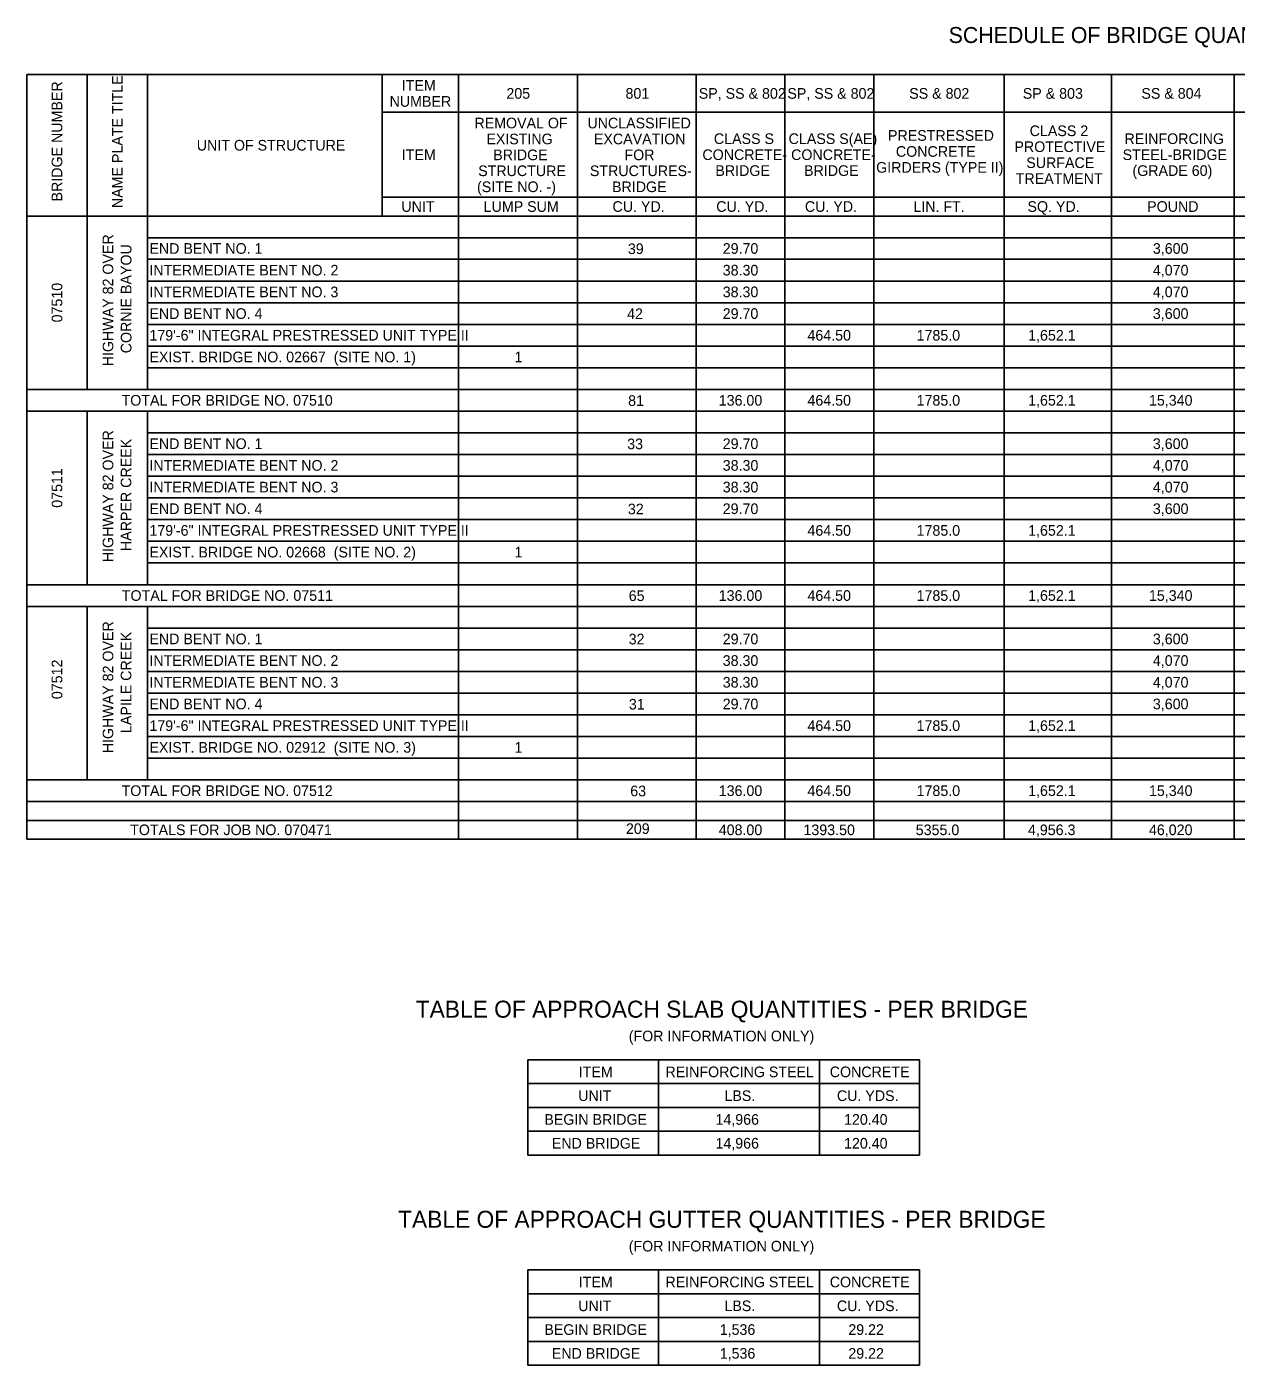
# Model space of a CAD drawing. Extents: x 978208 to 1610025, y 186514 to 1526540.
# Drawn here: x 978207.71 to 978221.92, y 1526243.05 to 1526258.78 of the extents above; entities that cross this region are included whole.
import ezdxf

# ---------------------------------------------------------------- set-up
doc = ezdxf.new("R2010")
doc.units = 0
for name, color, linetype in [('B_Dimensions', 7, 'Continuous'), ('B_Text', 7, 'Continuous'), ('B_Title Text', 7, 'Continuous')]:
    doc.layers.add(name, color=color, linetype=linetype)

msp = doc.modelspace()

# ---------------------------------------------------------------- linework, layer by layer
at = {"layer": 'B_Dimensions'}
msp.add_line((978207.713, 1526258.214), (978207.713, 1526258.214), dxfattribs=at)
at = {"layer": 'B_Text'}
for p, q in [((978207.713, 1526249.229), (978207.713, 1526258.214)), ((978207.713, 1526258.214), (978234.856, 1526258.214)), ((978208.422, 1526254.514), (978208.422, 1526258.214)), ((978209.131, 1526254.514), (978209.131, 1526258.214)), ((978211.886, 1526256.552), (978211.886, 1526258.214)), ((978212.784, 1526249.229), (978212.784, 1526258.214)), ((978214.18, 1526249.229), (978214.18, 1526258.214)), ((978215.576, 1526249.229), (978215.576, 1526258.214)), ((978216.618, 1526249.229), (978216.618, 1526258.214)), ((978217.66, 1526249.229), (978217.66, 1526258.214)), ((978219.191, 1526249.229), (978219.191, 1526258.214)), ((978220.452, 1526249.229), (978220.452, 1526258.214)), ((978221.892, 1526249.229), (978221.892, 1526258.214)), ((978211.886, 1526257.771), (978234.856, 1526257.771)), ((978211.886, 1526256.774), (978234.856, 1526256.774)), ((978207.713, 1526256.552), (978234.856, 1526256.552)), ((978209.131, 1526256.297), (978234.856, 1526256.297)), ((978209.131, 1526256.043), (978234.856, 1526256.043)), ((978209.131, 1526255.788), (978234.856, 1526255.788)), ((978209.131, 1526255.533), (978234.856, 1526255.533)), ((978209.131, 1526255.278), (978234.856, 1526255.278)), ((978209.131, 1526255.023), (978234.856, 1526255.023)), ((978209.131, 1526254.768), (978234.856, 1526254.768)), ((978207.713, 1526254.514), (978234.856, 1526254.514)), ((978207.713, 1526254.259), (978234.856, 1526254.259)), ((978208.422, 1526254.259), (978208.422, 1526252.22)), ((978209.131, 1526254.259), (978209.131, 1526252.22)), ((978209.131, 1526254.004), (978234.856, 1526254.004)), ((978209.131, 1526253.749), (978234.856, 1526253.749)), ((978209.131, 1526253.494), (978234.856, 1526253.494)), ((978209.131, 1526253.239), (978234.856, 1526253.239)), ((978209.131, 1526252.985), (978234.856, 1526252.985)), ((978209.131, 1526252.73), (978234.856, 1526252.73)), ((978209.131, 1526252.475), (978234.856, 1526252.475)), ((978207.713, 1526252.22), (978234.856, 1526252.22)), ((978207.713, 1526251.965), (978234.856, 1526251.965)), ((978208.422, 1526251.965), (978208.422, 1526249.927)), ((978209.131, 1526251.965), (978209.131, 1526249.927)), ((978209.131, 1526251.71), (978234.856, 1526251.71)), ((978209.131, 1526251.456), (978234.856, 1526251.456)), ((978209.131, 1526251.201), (978234.856, 1526251.201)), ((978209.131, 1526250.946), (978234.856, 1526250.946)), ((978209.131, 1526250.691), (978234.856, 1526250.691)), ((978209.131, 1526250.436), (978234.856, 1526250.436)), ((978209.131, 1526250.181), (978234.856, 1526250.181)), ((978207.713, 1526249.927), (978234.856, 1526249.927)), ((978207.713, 1526249.672), (978234.856, 1526249.672)), ((978207.713, 1526249.45), (978234.856, 1526249.45)), ((978207.713, 1526249.229), (978234.856, 1526249.229)), ((978213.598, 1526245.517), (978213.598, 1526246.637)), ((978213.598, 1526246.637), (978218.197, 1526246.637)), ((978215.131, 1526245.517), (978215.131, 1526246.637)), ((978217.024, 1526245.517), (978217.024, 1526246.637)), ((978218.197, 1526245.517), (978218.197, 1526246.637)), ((978213.598, 1526246.357), (978218.197, 1526246.357)), ((978213.598, 1526246.077), (978218.197, 1526246.077)), ((978213.598, 1526245.797), (978218.197, 1526245.797)), ((978213.598, 1526245.517), (978218.197, 1526245.517)), ((978213.598, 1526243.048), (978213.598, 1526244.168)), ((978213.598, 1526244.168), (978218.197, 1526244.168)), ((978215.131, 1526243.048), (978215.131, 1526244.168)), ((978217.024, 1526243.048), (978217.024, 1526244.168)), ((978218.197, 1526243.048), (978218.197, 1526244.168)), ((978213.598, 1526243.888), (978218.197, 1526243.888)), ((978213.598, 1526243.608), (978218.197, 1526243.608)), ((978213.598, 1526243.328), (978218.197, 1526243.328)), ((978213.598, 1526243.048), (978218.197, 1526243.048))]:
    msp.add_line(p, q, dxfattribs=at)

# ---------------------------------------------------------------- texts
for s, height, p in [('SCHEDULE OF BRIDGE QUANTITIES', 0.1875, (978218.54, 1526258.585)), ('ITEM', 0.125, (978212.118, 1526258.024)), ('NUMBER', 0.125, (978211.974, 1526257.836)), ('205', 0.125, (978213.346, 1526257.93)), ('801', 0.125, (978214.745, 1526257.93)), ('SP, SS & 802', 0.125, (978215.605, 1526257.93)), ('SP, SS & 802', 0.125, (978216.646, 1526257.93)), ('SS & 802', 0.125, (978218.077, 1526257.93)), ('SP & 803', 0.125, (978219.411, 1526257.93)), ('SS & 804', 0.125, (978220.804, 1526257.93)), ('REMOVAL OF', 0.1248, (978212.971, 1526257.582)), ('UNCLASSIFIED', 0.1248, (978214.298, 1526257.582)), ('EXISTING', 0.1248, (978213.111, 1526257.395)), ('EXCAVATION', 0.1248, (978214.374, 1526257.395)), ('CLASS S', 0.125, (978215.783, 1526257.398)), ('CLASS S(AE)', 0.125, (978216.661, 1526257.398)), ('    PRESTRESSED ', 0.125, (978217.642, 1526257.436)), ('CLASS 2', 0.125, (978219.492, 1526257.491)), ('REINFORCING', 0.125, (978220.605, 1526257.398)), ('UNIT OF STRUCTURE', 0.125, (978209.709, 1526257.321)), ('ITEM', 0.125, (978212.118, 1526257.21)), ('BRIDGE', 0.1248, (978213.191, 1526257.208)), ('FOR', 0.1248, (978214.733, 1526257.208)), ('CONCRETE-', 0.125, (978215.648, 1526257.21)), ('CONCRETE-', 0.125, (978216.69, 1526257.21)), ('      CONCRETE ', 0.125, (978217.642, 1526257.248)), ('PROTECTIVE', 0.125, (978219.313, 1526257.304)), ('STEEL-BRIDGE', 0.125, (978220.584, 1526257.21)), ('BRIDGE', 0.125, (978215.8, 1526257.023)), ('BRIDGE', 0.125, (978216.842, 1526257.023)), (' GIRDERS (TYPE II)', 0.125, (978217.642, 1526257.061)), ('SURFACE', 0.125, (978219.452, 1526257.116)), ('(GRADE 60)', 0.125, (978220.699, 1526257.023)), ('STRUCTURE', 0.1248, (978213.015, 1526257.021)), ('STRUCTURES-', 0.1248, (978214.327, 1526257.021)), ('TREATMENT', 0.125, (978219.328, 1526256.929)), ('(SITE NO. -)', 0.1248, (978213.001, 1526256.833)), ('BRIDGE', 0.1248, (978214.587, 1526256.833)), ('UNIT', 0.125, (978212.112, 1526256.601)), ('LUMP SUM', 0.125, (978213.079, 1526256.601)), ('CU. YD.', 0.125, (978214.592, 1526256.601)), ('CU. YD.', 0.125, (978215.811, 1526256.601)), ('CU. YD.', 0.125, (978216.852, 1526256.601)), ('LIN. FT.', 0.125, (978218.126, 1526256.601)), ('SQ. YD.', 0.125, (978219.466, 1526256.601)), ('POUND', 0.125, (978220.872, 1526256.601)), ('END BENT NO. 1', 0.125, (978209.153, 1526256.108)), ('39', 0.1248, (978214.773, 1526256.105)), ('29.70', 0.125, (978215.887, 1526256.108)), ('3,600', 0.125, (978220.939, 1526256.108)), ('INTERMEDIATE BENT NO. 2', 0.125, (978209.153, 1526255.853)), ('38.30', 0.125, (978215.887, 1526255.853)), ('4,070', 0.125, (978220.939, 1526255.853)), ('INTERMEDIATE BENT NO. 3', 0.125, (978209.153, 1526255.598)), ('38.30', 0.125, (978215.887, 1526255.598)), ('4,070', 0.125, (978220.939, 1526255.598)), ('END BENT NO. 4', 0.125, (978209.153, 1526255.343)), ('42', 0.1248, (978214.764, 1526255.341)), ('29.70', 0.125, (978215.887, 1526255.343)), ('3,600', 0.125, (978220.939, 1526255.343)), ('179\'-6" INTEGRAL PRESTRESSED UNIT TYPE II', 0.125, (978209.153, 1526255.088)), ('464.50', 0.125, (978216.882, 1526255.088)), ('1785.0', 0.125, (978218.164, 1526255.088)), ('1,652.1', 0.125, (978219.474, 1526255.088)), ('EXIST. BRIDGE NO. 02667  (SITE NO. 1)', 0.125, (978209.153, 1526254.833)), ('1', 0.125, (978213.442, 1526254.833)), ('TOTAL FOR BRIDGE NO. 07510', 0.125, (978208.826, 1526254.324)), ('81', 0.1248, (978214.776, 1526254.321)), ('136.00', 0.125, (978215.84, 1526254.324)), ('464.50', 0.125, (978216.882, 1526254.324)), ('1785.0', 0.125, (978218.164, 1526254.324)), ('1,652.1', 0.125, (978219.474, 1526254.324)), ('15,340', 0.125, (978220.893, 1526254.324)), ('END BENT NO. 1', 0.125, (978209.153, 1526253.814)), ('33', 0.1248, (978214.765, 1526253.812)), ('29.70', 0.125, (978215.887, 1526253.814)), ('3,600', 0.125, (978220.939, 1526253.814)), ('INTERMEDIATE BENT NO. 2', 0.125, (978209.153, 1526253.559)), ('38.30', 0.125, (978215.887, 1526253.559)), ('4,070', 0.125, (978220.939, 1526253.559)), ('INTERMEDIATE BENT NO. 3', 0.125, (978209.153, 1526253.304)), ('38.30', 0.125, (978215.887, 1526253.304)), ('4,070', 0.125, (978220.939, 1526253.304)), ('END BENT NO. 4', 0.125, (978209.153, 1526253.05)), ('32', 0.1248, (978214.773, 1526253.047)), ('29.70', 0.125, (978215.887, 1526253.05)), ('3,600', 0.125, (978220.939, 1526253.05)), ('179\'-6" INTEGRAL PRESTRESSED UNIT TYPE II', 0.125, (978209.153, 1526252.795)), ('464.50', 0.125, (978216.882, 1526252.795)), ('1785.0', 0.125, (978218.164, 1526252.795)), ('1,652.1', 0.125, (978219.474, 1526252.795)), ('EXIST. BRIDGE NO. 02668  (SITE NO. 2)', 0.125, (978209.153, 1526252.54)), ('1', 0.125, (978213.442, 1526252.54)), ('TOTAL FOR BRIDGE NO. 07511', 0.125, (978208.829, 1526252.03)), ('65', 0.1248, (978214.783, 1526252.028)), ('136.00', 0.125, (978215.84, 1526252.03)), ('464.50', 0.125, (978216.882, 1526252.03)), ('1785.0', 0.125, (978218.164, 1526252.03)), ('1,652.1', 0.125, (978219.474, 1526252.03)), ('15,340', 0.125, (978220.893, 1526252.03)), ('END BENT NO. 1', 0.125, (978209.153, 1526251.52)), ('32', 0.1248, (978214.782, 1526251.518)), ('29.70', 0.125, (978215.887, 1526251.52)), ('3,600', 0.125, (978220.939, 1526251.52)), ('INTERMEDIATE BENT NO. 2', 0.125, (978209.153, 1526251.266)), ('38.30', 0.125, (978215.887, 1526251.266)), ('4,070', 0.125, (978220.939, 1526251.266)), ('INTERMEDIATE BENT NO. 3', 0.125, (978209.153, 1526251.011)), ('38.30', 0.125, (978215.887, 1526251.011)), ('4,070', 0.125, (978220.939, 1526251.011)), ('END BENT NO. 4', 0.125, (978209.153, 1526250.756)), ('31', 0.1248, (978214.785, 1526250.753)), ('29.70', 0.125, (978215.887, 1526250.756)), ('3,600', 0.125, (978220.939, 1526250.756)), ('179\'-6" INTEGRAL PRESTRESSED UNIT TYPE II', 0.125, (978209.153, 1526250.501)), ('464.50', 0.125, (978216.882, 1526250.501)), ('1785.0', 0.125, (978218.164, 1526250.501)), ('1,652.1', 0.125, (978219.474, 1526250.501)), ('EXIST. BRIDGE NO. 02912  (SITE NO. 3)', 0.125, (978209.153, 1526250.246)), ('1', 0.125, (978213.442, 1526250.246)), ('TOTAL FOR BRIDGE NO. 07512', 0.125, (978208.826, 1526249.737)), ('63', 0.1248, (978214.801, 1526249.734)), ('136.00', 0.125, (978215.84, 1526249.737)), ('464.50', 0.125, (978216.882, 1526249.737)), ('1785.0', 0.125, (978218.164, 1526249.737)), ('1,652.1', 0.125, (978219.474, 1526249.737)), ('15,340', 0.125, (978220.893, 1526249.737)), ('TOTALS FOR JOB NO. 070471', 0.125, (978208.927, 1526249.277)), ('209', 0.1248, (978214.75, 1526249.291)), ('408.00', 0.125, (978215.84, 1526249.277)), ('1393.50', 0.125, (978216.835, 1526249.277)), ('5355.0', 0.125, (978218.154, 1526249.277)), ('4,956.3', 0.125, (978219.472, 1526249.277)), ('46,020', 0.125, (978220.893, 1526249.277)), ('(FOR INFORMATION ONLY)', 0.1248, (978214.783, 1526246.854)), ('ITEM', 0.1248, (978214.196, 1526246.433)), ('REINFORCING STEEL', 0.1248, (978215.214, 1526246.433)), ('CONCRETE', 0.1248, (978217.144, 1526246.433)), ('UNIT', 0.1248, (978214.19, 1526246.153)), ('LBS.', 0.1248, (978215.907, 1526246.153)), ('CU. YDS.', 0.1248, (978217.228, 1526246.153)), ('BEGIN BRIDGE', 0.1248, (978213.792, 1526245.874)), ('14,966', 0.1248, (978215.802, 1526245.874)), ('120.40', 0.1248, (978217.312, 1526245.874)), ('END BRIDGE', 0.1248, (978213.88, 1526245.594)), ('14,966', 0.1248, (978215.802, 1526245.594)), ('120.40', 0.1248, (978217.312, 1526245.594)), ('(FOR INFORMATION ONLY)', 0.1248, (978214.783, 1526244.385)), ('ITEM', 0.1248, (978214.196, 1526243.964)), ('REINFORCING STEEL', 0.1248, (978215.214, 1526243.964)), ('CONCRETE', 0.1248, (978217.144, 1526243.964)), ('UNIT', 0.1248, (978214.19, 1526243.684)), ('LBS.', 0.1248, (978215.907, 1526243.684)), ('CU. YDS.', 0.1248, (978217.228, 1526243.684)), ('BEGIN BRIDGE', 0.1248, (978213.792, 1526243.405)), ('1,536', 0.1248, (978215.852, 1526243.405)), ('29.22', 0.1248, (978217.362, 1526243.405)), ('END BRIDGE', 0.1248, (978213.88, 1526243.125)), ('1,536', 0.1248, (978215.852, 1526243.125)), ('29.22', 0.1248, (978217.362, 1526243.125))]:
    msp.add_text(s, height=height, dxfattribs=at).set_placement(p)
for s, p in [('BRIDGE NUMBER', (978208.13, 1526256.723)), ('NAME PLATE TITLE', (978208.839, 1526256.645)), ('HIGHWAY 82 OVER', (978208.729, 1526254.786)), ('CORNIE BAYOU', (978208.942, 1526254.939)), ('07510', (978208.13, 1526255.302)), ('HIGHWAY 82 OVER', (978208.729, 1526252.484)), ('HARPER CREEK', (978208.941, 1526252.615)), ('07511', (978208.13, 1526253.124)), ('HIGHWAY 82 OVER', (978208.729, 1526250.239)), ('LAPILE CREEK', (978208.941, 1526250.477)), ('07512', (978208.13, 1526250.875))]:
    msp.add_text(s, height=0.125, rotation=90, dxfattribs=at).set_placement(p)
at = {"layer": 'B_Title Text'}
for s, p in [('TABLE OF APPROACH SLAB QUANTITIES - PER BRIDGE', (978212.281, 1526247.132)), ('TABLE OF APPROACH GUTTER QUANTITIES - PER BRIDGE', (978212.074, 1526244.663))]:
    msp.add_text(s, height=0.19992, dxfattribs=at).set_placement(p)

doc.saveas('drawing.dxf')
